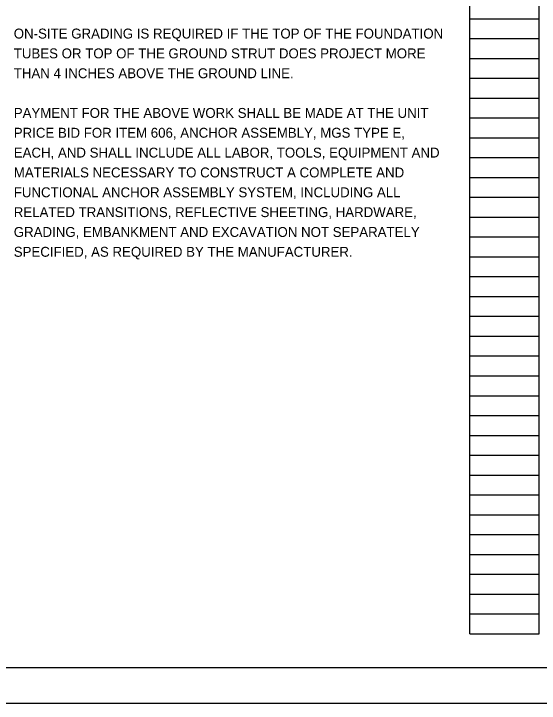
# Model space of a CAD drawing. Extents: x 0 to 37.9, y 0 to 22.
# Drawn here: x 17.24 to 24.66, y 0 to 9.73 of the extents above; entities that cross this region are included whole.
import ezdxf

# ---------------------------------------------------------------- set-up
doc = ezdxf.new("R2010")
doc.units = 0
for name, color, linetype in [('SH_Border', 7, 'Continuous'), ('SH_Cut_Line', 7, 'Continuous'), ('SH_Data', 7, 'Continuous'), ('SH_Text', 7, 'Continuous')]:
    doc.layers.add(name, color=color, linetype=linetype)

msp = doc.modelspace()

# ---------------------------------------------------------------- linework, layer by layer
at = {"layer": 'SH_Border'}
msp.add_lwpolyline([(1.5, 21.5), (33.5, 21.5), (33.5, 0.5), (1.5, 0.5)], close=True, dxfattribs=at)
at = {"layer": 'SH_Cut_Line'}
msp.add_lwpolyline([(0, 0), (34, 0), (34, 22), (0, 22)], close=True, dxfattribs=at)
at = {"layer": 'SH_Data'}
for p, q in [((23.68, 0.98), (23.68, 21.14)), ((24.66, 0.98), (24.66, 21.14)), ((23.68, 9.66), (24.66, 9.66)), ((23.68, 9.38), (24.66, 9.38)), ((23.68, 9.1), (24.66, 9.1)), ((23.68, 8.82), (24.66, 8.82)), ((23.68, 8.54), (24.66, 8.54)), ((23.68, 8.26), (24.66, 8.26)), ((23.68, 7.98), (24.66, 7.98)), ((23.68, 7.7), (24.66, 7.7)), ((23.68, 7.42), (24.66, 7.42)), ((23.68, 7.14), (24.66, 7.14)), ((23.68, 6.86), (24.66, 6.86)), ((23.68, 6.58), (24.66, 6.58)), ((23.68, 6.3), (24.66, 6.3)), ((23.68, 6.02), (24.66, 6.02)), ((23.68, 5.74), (24.66, 5.74)), ((23.68, 5.46), (24.66, 5.46)), ((23.68, 5.18), (24.66, 5.18)), ((23.68, 4.9), (24.66, 4.9)), ((23.68, 4.62), (24.66, 4.62)), ((23.68, 4.34), (24.66, 4.34)), ((23.68, 4.06), (24.66, 4.06)), ((23.68, 3.78), (24.66, 3.78)), ((23.68, 3.5), (24.66, 3.5)), ((23.68, 3.22), (24.66, 3.22)), ((23.68, 2.94), (24.66, 2.94)), ((23.68, 2.66), (24.66, 2.66)), ((23.68, 2.38), (24.66, 2.38)), ((23.68, 2.1), (24.66, 2.1)), ((23.68, 1.82), (24.66, 1.82)), ((23.68, 1.54), (24.66, 1.54)), ((23.68, 1.26), (24.66, 1.26)), ((23.68, 0.98), (24.66, 0.98))]:
    msp.add_line(p, q, dxfattribs=at)

# ---------------------------------------------------------------- texts
at = {"layer": 'SH_Text'}
for s, p in [('ON-SITE GRADING IS REQUIRED IF THE TOP OF THE FOUNDATION', (17.24, 9.38)), ('TUBES OR TOP OF THE GROUND STRUT DOES PROJECT MORE', (17.24, 9.1)), ('THAN 4 INCHES ABOVE THE GROUND LINE.', (17.24, 8.82)), ('PAYMENT FOR THE ABOVE WORK SHALL BE MADE AT THE UNIT', (17.24, 8.26)), ('PRICE BID FOR ITEM 606, ANCHOR ASSEMBLY, MGS TYPE E,', (17.24, 7.98)), ('EACH, AND SHALL INCLUDE ALL LABOR, TOOLS, EQUIPMENT AND', (17.24, 7.7)), ('MATERIALS NECESSARY TO CONSTRUCT A COMPLETE AND', (17.24, 7.42)), ('FUNCTIONAL ANCHOR ASSEMBLY SYSTEM, INCLUDING ALL', (17.24, 7.14)), ('RELATED TRANSITIONS, REFLECTIVE SHEETING, HARDWARE,', (17.24, 6.86)), ('GRADING, EMBANKMENT AND EXCAVATION NOT SEPARATELY', (17.24, 6.58)), ('SPECIFIED, AS REQUIRED BY THE MANUFACTURER.', (17.24, 6.3))]:
    msp.add_text(s, height=0.14, dxfattribs=at).set_placement(p)

doc.saveas('drawing.dxf')
